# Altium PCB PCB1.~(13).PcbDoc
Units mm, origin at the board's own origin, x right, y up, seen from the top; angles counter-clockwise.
Board outline 200.03 x 149.86 mm, 2 copper layers (Top Layer, Bottom Layer); 42 components, 40 nets, 233 pads, 0 vias.
Unrouted connection lines stored in the file: 148.
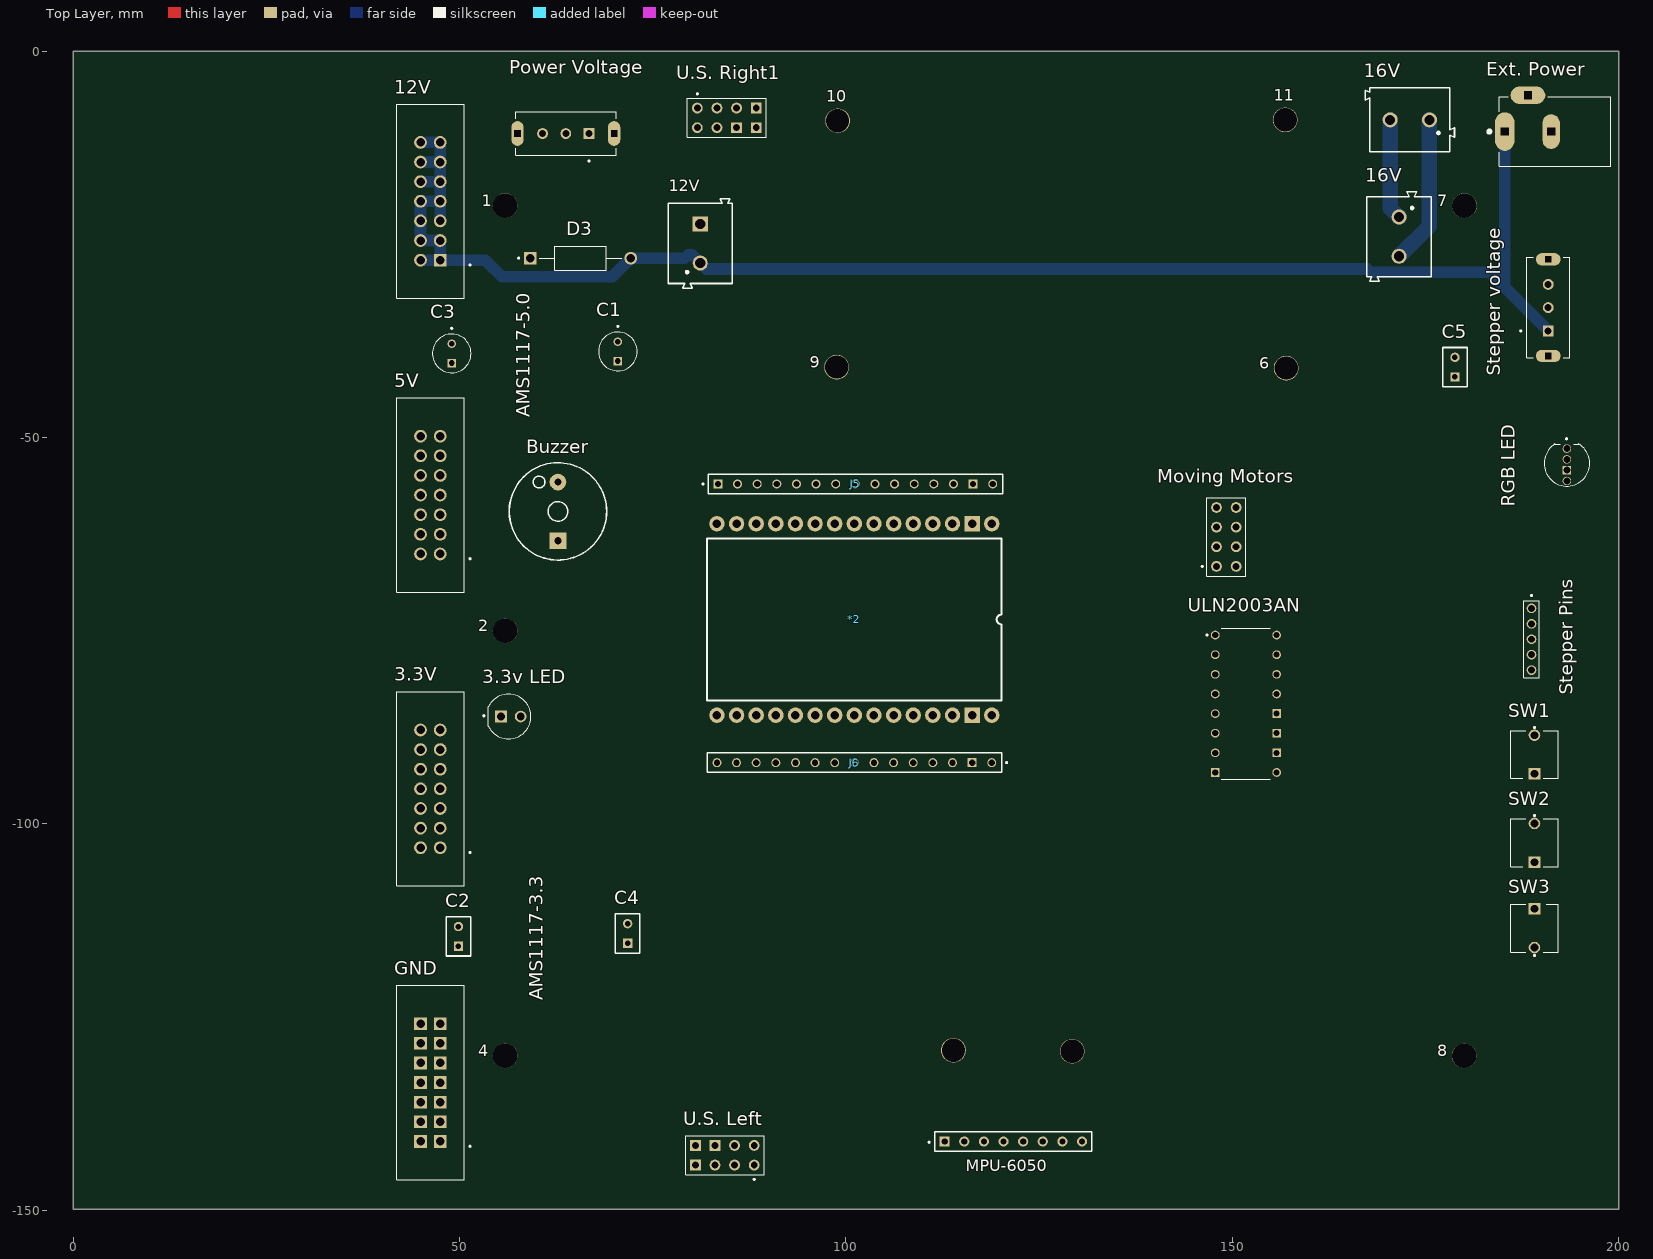
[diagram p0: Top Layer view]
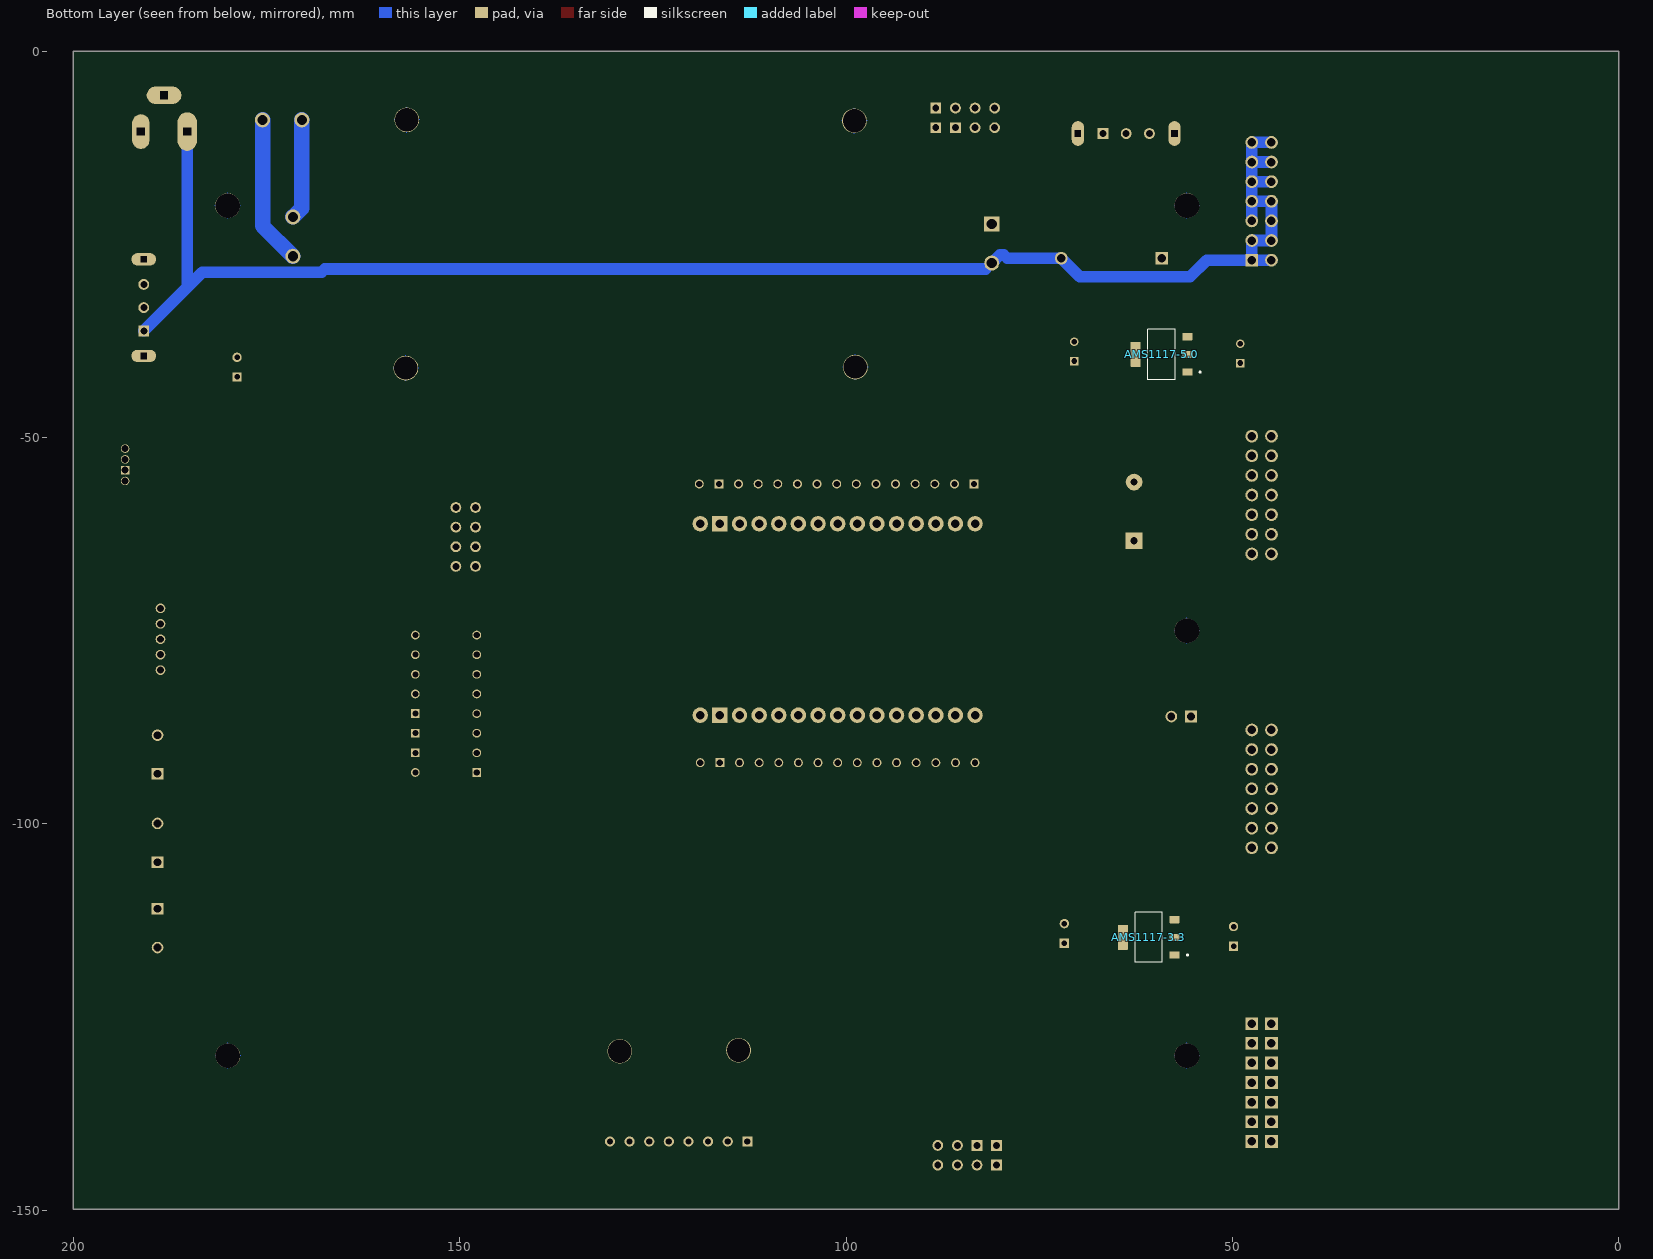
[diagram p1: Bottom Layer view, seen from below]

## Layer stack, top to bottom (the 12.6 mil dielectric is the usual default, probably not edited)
Top Solder: solder mask 0.0102, Solder Resist, Dk 3.5
Top Layer: signal copper 0.0356
Dielectric 1: dielectric 0.32, FR-4, Dk 4.8
Bottom Layer: signal copper 0.0356
Bottom Solder: solder mask 0.0102, Solder Resist, Dk 3.5

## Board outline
0,-149.86 200.025,-149.86 200.025,0 0,0

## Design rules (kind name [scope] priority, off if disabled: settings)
Clearance [All] p1: gap=0.254 ignorepadtopadclearanceinfootprint=FALSE except(0: Arc-Hole Track-Hole SMDPad-Hole THPad-Hole Via-Hole Fill-Hole Poly-Hole Region-Hole Text-Hole)
PolygonConnect [All] p1: connectstyle=Relief reliefconductorwidth=0.254 reliefentries=4 polygonreliefangle="90 Angle" airgapwidth=0.254
RoutingLayers [All] p1: top layer_v5=FALSE bottom layer_v5=TRUE
RoutingVias [All] p1: holewidth=0.711 width=1.27 viastyle="Through Hole" minholewidth=0.711 minwidth=1.27 maxholewidth=0.711 maxwidth=1.27
SolderMaskExpansion [All] p1: expansion=0.102 istentingtop=FALSE
Width [All] p1: maxlimit=2 minlimit=0.5 preferedwidth=1
29 further rules are at their usual default settings.

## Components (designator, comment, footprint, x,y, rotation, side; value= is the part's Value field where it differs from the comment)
1 "Mounting Hole" PCBComponent_1#1 55.9,-20 r0 top
2 "Mounting Hole" PCBComponent_1#1 55.9,-75 r0 top
3.3V "3.3v pin headers block" AMPHENOL_52601-S14-4LF#1 46.228,-95.462 r90 top (schematic designator J9)
"3.3v LED" "LED 5mm" "LED 5mm" 56.642,-86.106 r0 top (schematic designator D1)
4 "Mounting Hole" PCBComponent_1#1 55.9,-130 r0 top
5V "5v pin headers block" AMPHENOL_52601-S14-4LF#1 46.228,-57.446 r90 top (schematic designator J8)
6 "Mounting Hole" PCBComponent_1#2 156.972,-41.021 r90 top
7 "Mounting Hole" PCBComponent_1#1 180.025,-20 r90 top
8 "Mounting Hole" PCBComponent_1#1 180,-130 r0 top
9 "Mounting Hole" PCBComponent_1#2 98.806,-40.894 r90 top
10 "Mounting Hole" PCBComponent_1#2 98.933,-9.017 r0 top
11 "Mounting Hole" PCBComponent_1#2 156.845,-8.89 r0 top
12V "12v pin headers block" AMPHENOL_52601-S14-4LF#2 46.228,-19.431 r90 top (schematic designator J7)
12V "From Buck" 691213510002#1 81.153,-24.892 r90 top (schematic designator J3)
16V "Terminal Block" 691213510002#2 171.577,-24.003 r270 top (schematic designator J16V1)
16V "Terminal Block" 691213510002#2 172.974,-8.89 r180 top (schematic designator J16V2)
*2 "ESP32DEVKITV1" ESP32DEVKITV1 101.219,-72.841 r90 top
AMS1117-3.3 "AMS1117-3.3" SOT229P700X180-4N 60.833,-114.681 r0 bottom (schematic designator U2)
AMS1117-5.0 "AMS1117-5.0" SOT229P700X180-4N 59.182,-39.243 r0 bottom (schematic designator U1)
Buzzer "WST-1205S" WST-1205S 62.738,-59.563 r90 top (schematic designator J2)
C1 "CAP  33UF 50V RADIAL" "CAP  33UF 50V RADIAL" 70.485,-38.862 r270 top
C2 "Ceramic Capacitor 100nF" C320C 42.868,-107.554 r90 top
C3 "CAP  33UF 50V RADIAL" "CAP  33UF 50V RADIAL" 48.994,-39.116 r270 top
C4 "Ceramic Capacitor 100nF" C320C 64.755,-107.173 r90 top
C5 "Ceramic Capacitor 100nF" C320C 171.816,-33.894 r90 top
D3 "RL207" DIOAD1300W80L670D310 65.659,-26.797 r0 top
"Ext. Power" "DC Power Jack Female Socket" "DC Power Jack Female Socket" 185.262,-10.414 r0 top (schematic designator J1)
GND "GND pin headers block" AMPHENOL_52601-S14-4LF#3 46.228,-133.477 r90 top (schematic designator J10)
J5 "TS-115-T-A-1" SAMTEC_TS-115-T-A-1#1 101.219,-56.007 r0 top
J6 "TS-115-T-A-1" SAMTEC_TS-115-T-A-1#2 101.092,-92.075 r180 top
"Moving Motors" "Pin header female block 8 pin" "Pin header female block 8 pin"#1 149.225,-62.865 r90 top (schematic designator "Moving motors1")
MPU-6050 "MPU-6050" MPU-6050 111.252,-142.621 r90 top (schematic designator *)
"Power Voltage" "slide switch (5v,3.3v)" "Slide switch" 63.754,-10.668 r180 top (schematic designator S1)
"RGB LED" "common cathode" "LED RGB 5mm" 193.294,-53.34 r270 top (schematic designator D2)
"Stepper Pins" "Pin hreader 5 pins" "Pin hreader 5 pins" 188.722,-72.105 r270 top (schematic designator J4)
"Stepper voltage" "Slide switch" "Slide switch" 190.881,-33.195 r90 top (schematic designator S2)
SW1 "FSM8JRT" TE_FSM8JRT 189.103,-88.519 r270 top
SW2 "FSM8JRT" TE_FSM8JRT 189.103,-99.941 r270 top
SW3 "FSM8JRT" TE_FSM8JRT 189.103,-116.002 r90 top
"U.S. Left" "Pin header female block 8 pin" "Pin header female block 8 pin"#2 84.328,-142.875 r180 top (schematic designator "Ultrasonic Left1")
"U.S. Right1" "Pin header female block 8 pin" "Pin header female block 8 pin"#2 84.582,-8.636 r0 top (schematic designator "Ultrasonic Right1")
ULN2003AN "ULN2003AN" DIP794W45P254L1969H508Q16 151.765,-84.455 r0 top (schematic designator Q1)

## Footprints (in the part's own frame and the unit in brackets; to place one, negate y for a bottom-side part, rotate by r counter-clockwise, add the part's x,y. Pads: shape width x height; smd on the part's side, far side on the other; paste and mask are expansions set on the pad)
691213510002#1 [mm]
  round 1.95 hole 1.3: 1(-2.54,0)
  rect 1.95x1.95 hole 1.3: 2(2.54,0)
  silkscreen extent -5.78,-4.15 5.78,4.15, body extent -5.68,-3.94 5.68,4.16, height 10
691213510002#2 [mm]
  round 1.95 hole 1.3: 1(-2.54,0) 2(2.54,0)
  silkscreen extent -5.78,-4.15 5.78,4.15, body extent -5.68,-3.94 5.68,4.16, height 10
AMPHENOL_52601-S14-4LF#1 [mm]
  round 1.65 hole 1.1: 1(-7.62,-1.27) 2(-7.62,1.27) 3(-5.08,-1.27) 4(-5.08,1.27) 5(-2.54,-1.27) 6(-2.54,1.27) 7(0,-1.27) 8(0,1.27) 9(2.54,-1.27) 10(2.54,1.27) 11(5.08,-1.27) 12(5.08,1.27) 13(7.62,-1.27) 14(7.62,1.27)
  silkscreen extent -12.57,-5.23 12.57,4.38, body extent -12.57,-4.38 12.57,4.38, height 9.53
AMPHENOL_52601-S14-4LF#2 [mm]
  rect 1.65x1.65 hole 1.1: 1(-7.62,-1.27)
  round 1.65 hole 1.1: 2(-7.62,1.27) 3(-5.08,-1.27) 4(-5.08,1.27) 5(-2.54,-1.27) 6(-2.54,1.27) 7(0,-1.27) 8(0,1.27) 9(2.54,-1.27) 10(2.54,1.27) 11(5.08,-1.27) 12(5.08,1.27) 13(7.62,-1.27) 14(7.62,1.27)
  silkscreen extent -12.57,-5.23 12.57,4.38, body extent -12.57,-4.38 12.57,4.38, height 9.53
AMPHENOL_52601-S14-4LF#3 [mm]
  rect 1.65x1.65 hole 1.1: 1(-7.62,-1.27) 2(-7.62,1.27) 3(-5.08,-1.27) 4(-5.08,1.27) 5(-2.54,-1.27) 6(-2.54,1.27) 7(0,-1.27) 8(0,1.27) 9(2.54,-1.27) 10(2.54,1.27) 11(5.08,-1.27) 12(5.08,1.27) 13(7.62,-1.27) 14(7.62,1.27)
  silkscreen extent -12.57,-5.23 12.57,4.38, body extent -12.57,-4.38 12.57,4.38, height 9.53
C320C [mm]
  rect 1.21x1.21 hole 0.71: 1(-8.27,-7)
  round 1.21 hole 0.71: 2(-5.73,-7)
  silkscreen extent -9.54,-8.59 -4.46,-5.41, body extent -9.53,-8.57 -4.45,-5.4, height 7.1
"CAP  33UF 50V RADIAL" [mm]
  rect 1.1x1.1 hole 0.75: N(1.25,0)
  round 1.1 hole 0.75: P(-1.25,0)
  silkscreen extent -3.35,-2.5 2.5,2.5, body extent -2.49,-2.5 2.5,2.5, height 11
"DC Power Jack Female Socket" [mm]
  oval 2.5x5 hole 1 square: 1(0,0)
  oval 2.25x4.5 hole 1 square: 2(6,0)
  oval 4.5x2.25 hole 1 square: 3(3,4.7)
  silkscreen extent -2.2,-4.5 13.7,4.5, body extent -0.7,-4.5 13.7,4.9, height 11
DIOAD1300W80L670D310 [mm]
  round 1.65 hole 1.1: A(6.5,0)
  rect 1.65x1.65 hole 1.1: C(-6.5,0)
  silkscreen extent -8.1,-1.55 5.32,1.55, body extent -6.9,-1.95 6.9,1.65, height 3.6
DIP794W45P254L1969H508Q16 [mm]
  round 1.13 hole 0.78: 1(-3.97,8.89) 2(-3.97,6.35) 3(-3.97,3.81) 4(-3.97,1.27) 5(-3.97,-1.27) 6(-3.97,-3.81) 7(-3.97,-6.35) 9(3.97,-8.89) 13(3.97,1.27) 14(3.97,3.81) 15(3.97,6.35) 16(3.97,8.89)
  rect 1.13x1.13 hole 0.78: 8(-3.97,-8.89) 10(3.97,-6.35) 11(3.97,-3.81) 12(3.97,-1.27)
  silkscreen extent -5.13,-9.77 3.17,9.77, body extent -3.95,-10.54 3.95,10.79, height 5.08
ESP32DEVKITV1 [mm]
  round 2 hole 1.1: 1(11.684,-17.653) 3(11.684,-12.573) 4(11.684,-10.033) 5(11.684,-7.493) 6(11.684,-4.953) 7(11.684,-2.413) 8(11.684,0.127) 9(11.684,2.667) 10(11.684,5.207) 11(11.684,7.747) 12(11.684,10.287) 13(11.684,12.827) 14(11.684,15.367) 15(11.684,17.907) 16(-13.086,17.907) 17(-13.086,15.367) 18(-13.086,12.827) 19(-13.086,10.287) 20(-13.086,7.747) 21(-13.086,5.207) 22(-13.086,2.667) 23(-13.086,0.127) 24(-13.086,-2.413) 25(-13.086,-4.953) 26(-13.086,-7.493) 27(-13.086,-10.033) 28(-13.086,-12.573) 30(-13.086,-17.653)
  rect 2x2 hole 1.1: 2(11.684,-15.113) 29(-13.086,-15.113)
  silkscreen extent -11.2,-18.92 9.79,19.18, body extent -15.13,-28.49 13.86,24.48, height 8.36
"LED 5mm" [mm]
  round 1.508 hole 1: A(1.27,0)
  rect 1.508x1.508 hole 1: C(-1.27,0)
  silkscreen extent -3.6,-2.9 2.6,2.9, body extent -2.88,-2.9 2.51,2.9, height 12.1
"LED RGB 5mm" [mm]
  round 1.1 hole 0.9: 1(-1.905,0) 2(-0.508,0) 4(2.286,0)
  rect 1.1x1.1 hole 0.9: 3(0.889,0)
  silkscreen extent -3.27,-2.95 2.95,2.95, body extent -2.47,-3.05 2.98,2.84, height 9.6
MPU-6050 [mil]
  rect 52x52 hole 32: 01(60,-60)
  round 52 hole 32: 02(60,-160) 03(60,-260) 04(60,-360) 05(60,-460) 06(60,-560) 07(60,-660) 08(60,-760)
  round 125.98 hole 118.11: ""(520,-710) ""(525,-105)
  silkscreen extent 10,-810 110,23, body extent 15,-811 615,-9, height 612
PCBComponent_1#1 [mm]
  round 3.2 hole 3.2: ""(0,0)
  Bottom Layer lines w0.15: -1.651,0 1.649,0 ; 0,-1.651 0,1.649
PCBComponent_1#2 [mm]
  round 3.2 hole 3: ""(0,0)
  Bottom Layer lines w0.15: 0,1.649 0,-1.651 ; -1.651,0 1.649,0
"Pin header female block 8 pin"#1 [mm]
  round 1.398 hole 0.89: 1(-3.81,1.27) 2(-1.27,1.27) 3(1.27,1.27) 4(3.81,1.27) 5(-3.81,-1.27) 6(-1.27,-1.27) 7(1.27,-1.27) 8(3.81,-1.27)
  silkscreen extent -5.08,-2.52 5.08,3.21, body extent -5.08,-2.51 5.08,2.51, height 6.22
"Pin header female block 8 pin"#2 [mm]
  round 1.398 hole 0.89: 1(-3.81,1.27) 2(-1.27,1.27) 3(1.27,1.27) 5(-3.81,-1.27) 6(-1.27,-1.27)
  rect 1.398x1.398 hole 0.89: 4(3.81,1.27) 7(1.27,-1.27) 8(3.81,-1.27)
  silkscreen extent -5.08,-2.52 5.08,3.21, body extent -5.08,-2.51 5.08,2.51, height 6.22
"Pin hreader 5 pins" [mm]
  round 1.25 hole 0.9: 1(0,0) 2(2,0) 3(4,0) 4(6,0) 5(8,0)
  silkscreen extent -1.75,-1 9,1, body extent -1,-1 9,1, height 5.65
SAMTEC_TS-115-T-A-1#1 [mil]
  rect 45.78x45.78 hole 32: 01(-700,0) 14(600,0)
  round 45.78 hole 32: 02(-600,0) 03(-500,0) 04(-400,0) 05(-300,0) 06(-200,0) 07(-100,0) 08(0,0) 09(100,0) 10(200,0) 11(300,0) 12(400,0) 13(500,0) 15(700,0)
  silkscreen extent -780,-50 750,50, body extent -754,-50 754,50, height 326
SAMTEC_TS-115-T-A-1#2 [mil]
  round 45.78 hole 32: 01(-700,0) 03(-500,0) 04(-400,0) 05(-300,0) 06(-200,0) 07(-100,0) 08(0,0) 09(100,0) 10(200,0) 11(300,0) 12(400,0) 13(500,0) 14(600,0) 15(700,0)
  rect 45.78x45.78 hole 32: 02(-600,0)
  silkscreen extent -780,-50 750,50, body extent -754,-50 754,50, height 326
"Slide switch" [mm]
  rect 1.408x1.408 hole 0.9: 1(-3,0)
  round 1.408 hole 0.9: 2(0,0) 3(3,0)
  oval 1.6x3.2 hole 0.8 square: SH1(-6.25,0) SH2(6.25,0)
  silkscreen extent -6.5,-2.8 6.5,3.66, body extent -6.5,-5.8 6.5,2.8, height 6
SOT229P700X180-4N [mm]
  rrect15% 1.31x0.93 smd: 1(-3.345,2.29) 2(-3.345,0) 3(-3.345,-2.29)
  rrect15% 1.31x3.24 smd: 4(3.345,0)
  silkscreen extent -5.1,-3.25 1.75,3.25, body extent -3.5,-3.25 3.5,3.25, height 1.8
TE_FSM8JRT [mil]
  round 59 hole 39: 1(0,0)
  rect 59x59 hole 39: 2(197,0)
  silkscreen extent -44,-122 221,122, body extent -22,-122 222,122, height 372
WST-1205S [mil]
  rect 85x85 hole 36: NEG(-149.61,0)
  round 85 hole 36: POS(149.61,0)
  silkscreen extent -248,-248 248,248, body extent -236,-236 236,236, height 394

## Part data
3.3V 5V 12V GND: library part 52601-S14-4LF, Package=None
"3.3v LED": "Red 623nm LED Indication - Discrete 1.9V Radial", Package=None
12V: library part "Terminal Block", "2 Position Wire to Board Terminal Block Horizontal with Board 0.200 (5.08mm) Through Hole", Package=None
16V 16V: "2 Position Wire to Board Terminal Block Horizontal with Board 0.200 (5.08mm) Through Hole", Package=None
AMS1117-3.3 AMS1117-5.0 J5 J6 "Moving Motors" "Stepper Pins" "Stepper voltage" "U.S. Left" "U.S. Right1" ULN2003AN: Package=None
Buzzer: "BUZZER 2.3KHZ 4-6VDC", Package=None
C1 C3: "NHG-A", Package=None
C2 C4 C5: "0.1ÂµF Â±20% 50V Ceramic Capacitor Z5U Radial", Package="Radial KEMET"
D3: "Semiconductors and Actives, Power Diodes, Discretes (diodes, transistors, thyristors ...), Diodes", Package=None
"Ext. Power": "2.0 mm Center Pin, 2.5 A, Right Angle, Through Hole, Dc Power Jack Connector", Package=None
"Power Voltage": library part "Slide switch", Package=None
"RGB LED": library part "LED RGB 5mm", Package=None
SW1 SW2 SW3: "Tactile Switches PUSHBUTTON SWITCH TACT", Package=None

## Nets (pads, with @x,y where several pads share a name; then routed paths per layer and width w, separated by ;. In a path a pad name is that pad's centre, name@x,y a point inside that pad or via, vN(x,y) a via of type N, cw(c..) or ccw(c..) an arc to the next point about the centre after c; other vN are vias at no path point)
3.3V: 3.3V.1 3.3V.2 3.3V.3 3.3V.4 3.3V.5 3.3V.6 3.3V.7 3.3V.8 3.3V.9 3.3V.10 3.3V.11 3.3V.12 3.3V.13 3.3V.14 *2.1 AMS1117-3.3.2 C2.2 J5.15 MPU-6050.01
+5: 5V.1 5V.2 5V.3 5V.4 5V.5 5V.6 5V.7 5V.8 5V.9 5V.10 5V.11 5V.12 5V.13 5V.14 "Power Voltage.1" "Power Voltage.2" "Stepper voltage.3" "U.S. Left.1" "U.S. Left.5" "U.S. Right1.1" "U.S. Right1.5" AMS1117-5.0.2 C1.P
+12: 12V.1 12V.2@44.958,-27.051 12V.3 12V.4 12V.5 12V.6 12V.7 12V.8 12V.9 12V.10 12V.11 12V.12 12V.13 12V.14 "Ext. Power.1" "Stepper voltage.1" D3.A | length 202.7
  Bottom Layer w1: 79.172,-26.797 79.604,-26.365 ; 12V.1@81.153,-27.432 81.915,-28.194 ; 167.437,-28.194 167.869,-28.626
  Bottom Layer w1.5: 12V.2@44.958,-27.051 12V.1@47.498,-27.051 ; 12V.10 12V.9 ; 12V.12 12V.11 ; 12V.14 12V.13 12V.11 ; 12V.5 12V.7 ; 79.172,-26.797 D3.A 69.746,-29.21 55.499,-29.21 53.34,-27.051 12V.1@47.498,-27.051 ; 79.604,-26.365 80.086,-26.365 12V.1@81.153,-27.432 ; 81.915,-28.194 167.437,-28.194 ; 167.869,-28.626 183.312,-28.626 185.262,-30.576 ; 185.262,-10.414 185.262,-30.576 ; 190.881,-36.195 185.262,-30.576 ; 12V.1@47.498,-27.051 12V.3 12V.4 12V.6 12V.8 12V.7 ; 12V.7 12V.9 ; 12V.9 12V.11
GND: 12V.2@81.153,-22.352 "3.3v LED.C" "Ext. Power.2" "Ext. Power.3" "RGB LED.3" "U.S. Left.4" "U.S. Left.7" "U.S. Left.8" "U.S. Right1.4" "U.S. Right1.7" "U.S. Right1.8" *2.2 *2.29 AMS1117-3.3.1 AMS1117-5.0.1 Buzzer.NEG C1.N C2.1 C3.N C4.1 C5.1 GND.1 GND.2 GND.3 GND.4 GND.5 GND.6 GND.7 GND.8 GND.9 GND.10 GND.11 GND.12 GND.13 GND.14 J5.14 J6.02 MPU-6050.02 SW1.2 SW2.2 SW3.2 ULN2003AN.8 ULN2003AN.10 ULN2003AN.11 ULN2003AN.12
Net*2_3: *2.3 J5.13 ULN2003AN.4
Net*2_4: "RGB LED.2" *2.4 J5.12
Net*2_5: "Moving Motors.8" *2.5 J5.11
Net*2_6: "Moving Motors.7" *2.6 J5.10
Net*2_7: "Moving Motors.6" *2.7 J5.09
Net*2_8: "U.S. Right1.6" *2.8 J5.08
Net*2_9: "U.S. Right1.3" *2.9 J5.07
Net*2_10: "U.S. Right1.2" *2.10 J5.06
Net*2_11: *2.11 J5.05 MPU-6050.04
Net*2_12: "RGB LED.4" *2.12 J5.04
Net*2_13: "RGB LED.1" *2.13 J5.03
Net*2_14: *2.14 J5.02 MPU-6050.03
Net*2_15: *2.15 Buzzer.POS J5.01
Net*2_16: *2.16 J6.15
Net*2_17: *2.17 J6.14 SW1.1
Net*2_18: *2.18 J6.13 SW2.1
Net*2_19: *2.19 J6.12 SW3.1
Net*2_20: "U.S. Left.3" *2.20 J6.11
Net*2_21: "U.S. Left.2" *2.21 J6.10
Net*2_22: "U.S. Left.6" *2.22 J6.09
Net*2_23: "Moving Motors.1" *2.23 J6.08
Net*2_24: "Moving Motors.3" *2.24 J6.07
Net*2_25: "Moving Motors.2" *2.25 J6.06
Net*2_26: *2.26 J6.05 ULN2003AN.1
Net*2_27: *2.27 J6.04 ULN2003AN.2
Net*2_28: *2.28 J6.03 ULN2003AN.3
Net*2_30: *2.30 J6.01
NetC3_P: AMS1117-5.0.3 C3.P D3.C
NetC4_2: "3.3v LED.A" "Power Voltage.3" AMS1117-3.3.3 C4.2
NetC5_2: "Stepper Pins.1" "Stepper voltage.2" C5.2 ULN2003AN.9
NetJ4_2: "Stepper Pins.2" ULN2003AN.16
NetJ4_3: "Stepper Pins.3" ULN2003AN.15
NetJ4_4: "Stepper Pins.4" ULN2003AN.14
NetJ4_5: "Stepper Pins.5" ULN2003AN.13
NetJ16V1_1: 16V.1@171.577,-21.463 16V.2@170.434,-8.89 | length 13
  Bottom Layer w2: 16V.2@170.434,-8.89 170.434,-20.32 16V.1@171.577,-21.463
NetJ16V1_2: 16V.1@175.514,-8.89 16V.2@171.577,-26.543 | length 19.3
  Bottom Layer w2: 16V.2@171.577,-26.543 175.514,-22.606 16V.1@175.514,-8.89
pads on no net: 1. 2. 4. 6. 7. 8. 9. 10. 11. "Moving Motors.4" "Moving Motors.5" "Power Voltage.SH1" "Power Voltage.SH2" "Stepper voltage.SH1" "Stepper voltage.SH2" AMS1117-3.3.4 AMS1117-5.0.4 MPU-6050. MPU-6050.05 MPU-6050.06 MPU-6050.07 MPU-6050.08 ULN2003AN.5 ULN2003AN.6 ULN2003AN.7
